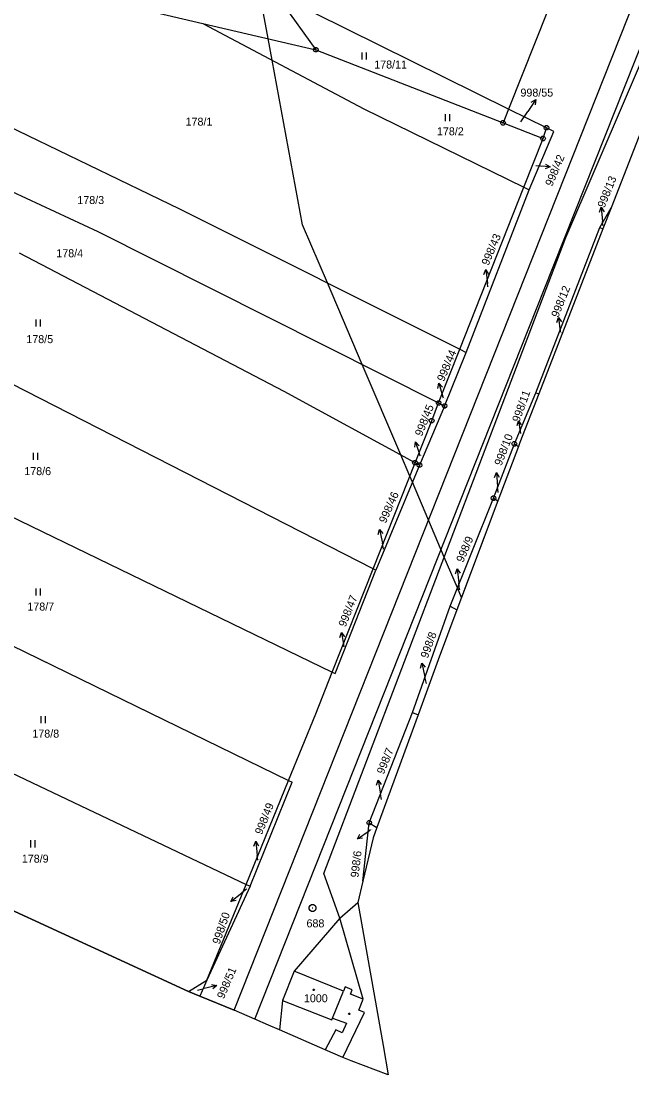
# Model space of a CAD drawing. Extents: x -755359 to -754474, y -1162585 to -1161655.
# Drawn here: x -755045.7 to -754916, y -1162585.2 to -1162361.4 of the extents above; entities that cross this region are included whole.
import ezdxf

# ---------------------------------------------------------------- set-up
doc = ezdxf.new("R2010")
doc.units = 0
for name, color, linetype in [('Vrstva 1', 7, 'Continuous'), ('Vrstva 11', 7, 'Continuous'), ('Vrstva 12', 7, 'Continuous'), ('Vrstva 2', 7, 'Continuous'), ('Vrstva 3', 7, 'Continuous'), ('Vrstva 4', 7, 'Continuous'), ('Vrstva 5', 7, 'Continuous'), ('Vrstva 6', 7, 'Continuous'), ('Vrstva 7', 7, 'Continuous'), ('Vrstva 8', 7, 'Continuous')]:
    doc.layers.add(name, color=color, linetype=linetype)

msp = doc.modelspace()

# ---------------------------------------------------------------- linework, layer by layer
at = {"layer": 'Vrstva 1'}
for p, q in [((-754930.02, -1162407.36), (-754870.17, -1162267.96)), ((-755096.49, -1162341), (-755007.12, -1162361.91)), ((-754942.18, -1162380.1), (-754991.59, -1162355.66)), ((-754991.59, -1162355.66), (-754983.11, -1162367.53)), ((-754933.79, -1162358.94), (-754942.18, -1162380.1)), ((-754904.19, -1162359.38), (-754920.39, -1162401.05)), ((-755007.12, -1162361.91), (-754972.93, -1162380.07)), ((-755007.12, -1162361.91), (-754983.11, -1162367.53)), ((-754983.11, -1162367.53), (-754943.35, -1162383.04)), ((-755065.93, -1162375.26), (-755012.09, -1162401.26)), ((-754972.93, -1162380.07), (-754938.92, -1162396.68)), ((-754942.18, -1162380.1), (-754943.35, -1162383.04)), ((-754934.1, -1162384.09), (-754942.18, -1162380.1)), ((-754943.35, -1162383.04), (-754934.85, -1162386.36)), ((-754934.85, -1162386.36), (-754934.1, -1162384.09)), ((-754932.57, -1162384.85), (-754934.1, -1162384.09)), ((-754938.92, -1162396.68), (-754934.85, -1162386.36)), ((-754937.81, -1162397.22), (-754932.57, -1162384.85)), ((-755066.17, -1162388.99), (-755029.41, -1162406.11)), ((-754952.51, -1162431.09), (-754938.92, -1162396.68)), ((-754951.16, -1162431.76), (-754937.81, -1162397.22)), ((-754938.92, -1162396.68), (-754937.81, -1162397.22)), ((-755012.09, -1162401.26), (-754952.51, -1162431.09)), ((-754922.76, -1162405.23), (-754920.39, -1162401.05)), ((-754920.39, -1162401.05), (-754922.13, -1162405.53)), ((-755029.41, -1162406.11), (-754957.02, -1162442.51)), ((-754936.37, -1162440.35), (-754922.76, -1162405.23)), ((-754922.13, -1162405.53), (-754935.75, -1162440.55)), ((-754922.76, -1162405.23), (-754922.13, -1162405.53)), ((-754981.37, -1162542.41), (-754930.02, -1162407.36)), ((-754989.82, -1162440.1), (-755046.04, -1162410.7)), ((-754957.02, -1162442.51), (-754952.51, -1162431.09)), ((-754952.51, -1162431.09), (-754951.16, -1162431.76)), ((-754955.75, -1162443.15), (-754951.16, -1162431.76)), ((-754970.94, -1162477.7), (-755047.73, -1162438.47)), ((-754962.03, -1162455.19), (-754989.82, -1162440.1)), ((-754958.5, -1162446.27), (-754957.02, -1162442.51)), ((-754957.02, -1162442.51), (-754955.75, -1162443.15)), ((-754940.94, -1162451.2), (-754936.37, -1162440.35)), ((-754935.75, -1162440.55), (-754939.77, -1162450.9)), ((-754936.37, -1162440.35), (-754935.75, -1162440.55)), ((-754955.75, -1162443.15), (-754961.09, -1162455.7)), ((-754962.03, -1162455.19), (-754958.5, -1162446.27)), ((-755081.44, -1162450.28), (-754979.63, -1162499.65)), ((-754945.37, -1162462.72), (-754940.94, -1162451.2)), ((-754940.94, -1162451.2), (-754940.08, -1162451.73)), ((-754939.77, -1162450.9), (-754940.08, -1162451.73)), ((-754940.08, -1162451.73), (-754944.44, -1162463.31)), ((-754970.94, -1162477.7), (-754962.03, -1162455.19)), ((-754961.09, -1162455.7), (-754970.36, -1162478)), ((-754961.09, -1162455.7), (-754962.03, -1162455.19)), ((-754954.58, -1162485.64), (-754945.37, -1162462.72)), ((-754944.44, -1162463.31), (-754953.13, -1162486.42)), ((-754945.37, -1162462.72), (-754944.44, -1162463.31)), ((-754979.63, -1162499.65), (-754970.94, -1162477.7)), ((-754979.01, -1162499.95), (-754970.36, -1162478)), ((-754970.36, -1162478), (-754970.94, -1162477.7)), ((-754962.59, -1162508.22), (-754954.58, -1162485.64)), ((-754953.13, -1162486.42), (-754957.12, -1162497.02)), ((-754954.58, -1162485.64), (-754953.13, -1162486.42)), ((-755054.02, -1162490.91), (-754988.9, -1162522.63)), ((-754957.12, -1162497.02), (-754961.39, -1162508.73)), ((-754983.12, -1162508.48), (-754979.63, -1162499.65)), ((-754979.63, -1162499.65), (-754979.01, -1162499.95)), ((-755083.94, -1162503.85), (-754997.93, -1162544.71)), ((-754988.9, -1162522.63), (-754983.12, -1162508.48)), ((-754971.75, -1162531.64), (-754962.59, -1162508.22)), ((-754961.39, -1162508.73), (-754970.12, -1162532.66)), ((-754962.59, -1162508.22), (-754961.39, -1162508.73)), ((-754997.93, -1162544.71), (-754988.9, -1162522.63)), ((-754997.07, -1162545.12), (-754988.1, -1162523.02)), ((-754988.9, -1162522.63), (-754988.1, -1162523.02)), ((-754973.09, -1162544.04), (-754971.75, -1162531.64)), ((-754971.75, -1162531.64), (-754970.12, -1162532.66)), ((-754970.12, -1162532.66), (-754970.91, -1162534.82)), ((-754970.91, -1162534.82), (-754973.09, -1162544.04)), ((-755064.06, -1162542.65), (-755010.16, -1162567.43)), ((-754978.01, -1162551.88), (-754981.37, -1162542.41)), ((-755006.25, -1162565.05), (-754997.93, -1162544.71)), ((-754997.07, -1162545.12), (-755006.25, -1162565.05)), ((-754997.93, -1162544.71), (-754997.07, -1162545.12)), ((-754973.09, -1162544.04), (-754974.17, -1162548.58)), ((-754978.01, -1162551.88), (-754974.17, -1162548.58)), ((-754974.17, -1162548.58), (-754968.81, -1162578.95)), ((-754978.01, -1162551.88), (-754987.73, -1162563.16)), ((-754987.73, -1162563.16), (-754990.19, -1162569.34)), ((-755010.16, -1162567.43), (-755006.25, -1162565.05)), ((-755006.25, -1162565.05), (-755007.72, -1162568.42)), ((-755010.16, -1162567.43), (-755007.72, -1162568.42)), ((-755007.72, -1162568.42), (-755000.46, -1162571.42)), ((-754990.19, -1162569.34), (-754990.79, -1162575.62)), ((-754996.07, -1162573.33), (-755000.46, -1162571.42)), ((-754993.17, -1162574.58), (-754996.07, -1162573.33)), ((-754990.79, -1162575.62), (-754993.17, -1162574.58)), ((-754981.12, -1162579.81), (-754990.79, -1162575.62)), ((-754968.81, -1162578.95), (-754967.71, -1162585.17)), ((-754977.36, -1162581.44), (-754981.12, -1162579.81)), ((-754975.59, -1162582.21), (-754977.36, -1162581.44)), ((-754967.71, -1162585.17), (-754975.59, -1162582.21))]:
    msp.add_line(p, q, dxfattribs=at)
at = {"layer": 'Vrstva 11'}
for p, q in [((-754993.26, -1162365.15), (-754995.39, -1162353.66)), ((-754904.19, -1162359.38), (-754920.39, -1162401.05)), ((-754992.41, -1162369.72), (-754993.26, -1162365.15)), ((-754985.92, -1162404.66), (-754992.41, -1162369.72)), ((-754920.39, -1162401.05), (-754922.13, -1162405.53)), ((-754980.66, -1162416.99), (-754985.92, -1162404.66)), ((-754922.13, -1162405.53), (-754935.75, -1162440.55)), ((-754973.27, -1162434.34), (-754980.66, -1162416.99)), ((-754965.08, -1162453.53), (-754973.27, -1162434.34)), ((-754935.75, -1162440.55), (-754939.77, -1162450.9)), ((-754939.77, -1162450.9), (-754940.08, -1162451.73)), ((-754963.16, -1162458.04), (-754965.08, -1162453.53)), ((-754940.08, -1162451.73), (-754944.44, -1162463.31)), ((-754962.6, -1162459.34), (-754963.16, -1162458.04)), ((-754955.83, -1162475.23), (-754962.6, -1162459.34)), ((-754944.44, -1162463.31), (-754952.16, -1162483.84)), ((-754953.03, -1162481.79), (-754955.83, -1162475.23)), ((-754952.16, -1162483.84), (-754953.03, -1162481.79)), ((-754952.16, -1162483.84), (-754953.13, -1162486.42)), ((-754953.13, -1162486.42), (-754957.12, -1162497.02)), ((-754957.12, -1162497.02), (-754961.39, -1162508.73)), ((-754961.39, -1162508.73), (-754970.12, -1162532.66)), ((-754970.12, -1162532.66), (-754970.91, -1162534.82)), ((-754970.91, -1162534.82), (-754973.09, -1162544.04)), ((-755010.16, -1162567.43), (-755064.06, -1162542.65)), ((-754973.09, -1162544.04), (-754974.17, -1162548.58)), ((-754974.17, -1162548.58), (-754968.81, -1162578.95)), ((-755007.72, -1162568.42), (-755010.16, -1162567.43)), ((-755000.46, -1162571.42), (-755007.72, -1162568.42)), ((-754996.07, -1162573.33), (-755000.46, -1162571.42)), ((-754993.17, -1162574.58), (-754996.07, -1162573.33)), ((-754990.79, -1162575.62), (-754993.17, -1162574.58)), ((-754981.12, -1162579.81), (-754990.79, -1162575.62)), ((-754968.81, -1162578.95), (-754967.71, -1162585.17)), ((-754977.36, -1162581.44), (-754981.12, -1162579.81)), ((-754975.59, -1162582.21), (-754977.36, -1162581.44)), ((-754967.71, -1162585.17), (-754975.59, -1162582.21))]:
    msp.add_line(p, q, dxfattribs=at)
at = {"layer": 'Vrstva 12'}
for p, q in [((-754987.73, -1162563.16), (-754990.19, -1162569.34)), ((-754977.24, -1162567.4), (-754987.73, -1162563.16)), ((-754979.54, -1162573.11), (-754977.24, -1162567.4)), ((-754990.19, -1162569.34), (-754979.67, -1162573.44)), ((-754979.67, -1162573.44), (-754979.54, -1162573.11))]:
    msp.add_line(p, q, dxfattribs=at)
at = {"layer": 'Vrstva 3'}
for p, q in [((-754973.32, -1162368.07), (-754973.32, -1162369.57)), ((-754972.32, -1162369.57), (-754972.32, -1162368.07)), ((-754955.63, -1162381.19), (-754955.63, -1162382.69)), ((-754954.63, -1162382.69), (-754954.63, -1162381.19)), ((-755042.57, -1162424.8), (-755042.57, -1162426.3)), ((-755041.57, -1162426.3), (-755041.57, -1162424.8)), ((-755043.16, -1162453.08), (-755043.16, -1162454.58)), ((-755042.16, -1162454.58), (-755042.16, -1162453.08)), ((-755042.6, -1162481.9), (-755042.6, -1162483.4)), ((-755041.6, -1162483.4), (-755041.6, -1162481.9)), ((-755041.54, -1162509), (-755041.54, -1162510.5)), ((-755040.54, -1162510.5), (-755040.54, -1162509)), ((-755043.69, -1162535.35), (-755043.69, -1162536.85)), ((-755042.69, -1162536.85), (-755042.69, -1162535.35))]:
    msp.add_line(p, q, dxfattribs=at)
at = {"layer": 'Vrstva 4'}
for p, q in [((-754973.06, -1162569.09), (-754978.01, -1162551.88)), ((-754977.24, -1162567.4), (-754987.73, -1162563.16)), ((-754979.54, -1162573.11), (-754977.24, -1162567.4)), ((-754976.86, -1162566.48), (-754977.24, -1162567.4)), ((-754975.36, -1162567.08), (-754976.86, -1162566.48)), ((-754975.74, -1162568.01), (-754975.36, -1162567.08)), ((-754990.19, -1162569.34), (-754979.67, -1162573.44)), ((-754973.06, -1162569.09), (-754975.74, -1162568.01)), ((-754974, -1162571.4), (-754973.06, -1162569.09)), ((-754977.36, -1162581.44), (-754972.76, -1162571.89)), ((-754972.76, -1162571.89), (-754974, -1162571.4)), ((-754979.67, -1162573.44), (-754979.54, -1162573.11)), ((-754979.54, -1162573.11), (-754976.57, -1162574.2)), ((-754976.57, -1162574.2), (-754977.49, -1162576.26)), ((-754978.86, -1162575.61), (-754981.12, -1162579.81)), ((-754977.49, -1162576.26), (-754978.86, -1162575.61))]:
    msp.add_line(p, q, dxfattribs=at)
at = {"layer": 'Vrstva 5'}
for points in [[(-754983.45, -1162566.98), (-754983.36, -1162567.13), (-754983.45, -1162567.28), (-754983.63, -1162567.28), (-754983.72, -1162567.13), (-754983.63, -1162566.98)], [(-754975.92, -1162572.07), (-754975.83, -1162572.22), (-754975.92, -1162572.37), (-754976.1, -1162572.37), (-754976.19, -1162572.22), (-754976.1, -1162572.07)]]:
    msp.add_lwpolyline(points, close=True, dxfattribs=at)
at = {"layer": 'Vrstva 6'}
for p, q in [((-755000.46, -1162571.42), (-754786.74, -1162032.64)), ((-754934.61, -1162418.42), (-754899.91, -1162330.95)), ((-754996.07, -1162573.33), (-754934.61, -1162418.42))]:
    msp.add_line(p, q, dxfattribs=at)
at = {"layer": 'Vrstva 7'}
for p, q in [((-754936.385, -1162378.094), (-754938.05, -1162380.59)), ((-754939.56, -1162382.84), (-754938.05, -1162380.59)), ((-754933.368, -1162392.353), (-754936.36, -1162392.13)), ((-754922.471, -1162400.961), (-754922.21, -1162403.95)), ((-754922.14, -1162404.8), (-754922.21, -1162403.95)), ((-754947.025, -1162414.192), (-754946.66, -1162417.17)), ((-754946.58, -1162417.83), (-754946.66, -1162417.17)), ((-754931.545, -1162424.332), (-754931.18, -1162427.31)), ((-754931.15, -1162427.55), (-754931.18, -1162427.31)), ((-754956.998, -1162438.311), (-754956.12, -1162441.18)), ((-754956.02, -1162441.51), (-754956.12, -1162441.18)), ((-754940.041, -1162446.317), (-754939.66, -1162449.02)), ((-754961.917, -1162450.777), (-754960.99, -1162453.63)), ((-754960.96, -1162453.72), (-754960.99, -1162453.63)), ((-754944.751, -1162457.291), (-754944.49, -1162460.28)), ((-754944.37, -1162461.51), (-754944.49, -1162460.28)), ((-754969.592, -1162469.345), (-754968.97, -1162472.28)), ((-754968.71, -1162473.56), (-754968.97, -1162472.28)), ((-754953.074, -1162477.727), (-754952.76, -1162480.71)), ((-754952.6, -1162482.15), (-754952.76, -1162480.71)), ((-754977.659, -1162491.217), (-754977.19, -1162494.18)), ((-754977.17, -1162494.31), (-754977.19, -1162494.18)), ((-754960.625, -1162497.757), (-754959.95, -1162500.68)), ((-754959.63, -1162502.08), (-754959.95, -1162500.68)), ((-754969.882, -1162522.586), (-754969.36, -1162525.54)), ((-754969.16, -1162526.69), (-754969.36, -1162525.54)), ((-754974.277, -1162535.017), (-754971.79, -1162533.34)), ((-754971.47, -1162533.12), (-754971.79, -1162533.34)), ((-754995.854, -1162535.567), (-754995.54, -1162538.55)), ((-754995.44, -1162539.55), (-754995.54, -1162538.55)), ((-755001.154, -1162548.337), (-754998.79, -1162546.49)), ((-754997.81, -1162545.72), (-754998.79, -1162546.49)), ((-755008.2, -1162567.18), (-755007.07, -1162566.91)), ((-755004.159, -1162566.183), (-755007.07, -1162566.91))]:
    msp.add_line(p, q, dxfattribs=at)
for points in [[(-754937.356, -1162378.649), (-754936.385, -1162378.094), (-754936.524, -1162379.204)], [(-754934.328, -1162391.78), (-754933.368, -1162392.353), (-754934.403, -1162392.777)], [(-754922.882, -1162402.001), (-754922.471, -1162400.961), (-754921.886, -1162401.914)], [(-754947.4, -1162415.246), (-754947.025, -1162414.192), (-754946.407, -1162415.124)], [(-754931.92, -1162425.386), (-754931.545, -1162424.332), (-754930.927, -1162425.264)], [(-754957.183, -1162439.414), (-754956.998, -1162438.311), (-754956.227, -1162439.121)], [(-754940.365, -1162447.281), (-754940.041, -1162446.317), (-754939.463, -1162447.154)], [(-754962.083, -1162451.882), (-754961.917, -1162450.777), (-754961.132, -1162451.573)], [(-754945.162, -1162458.331), (-754944.751, -1162457.291), (-754944.166, -1162458.244)], [(-754969.874, -1162470.427), (-754969.592, -1162469.345), (-754968.896, -1162470.22)], [(-754953.467, -1162478.773), (-754953.074, -1162477.727), (-754952.472, -1162478.669)], [(-754977.997, -1162492.283), (-754977.659, -1162491.217), (-754977.009, -1162492.126)], [(-754960.887, -1162498.844), (-754960.625, -1162497.757), (-754959.913, -1162498.619)], [(-754970.201, -1162523.658), (-754969.882, -1162522.586), (-754969.216, -1162523.483)], [(-754973.169, -1162534.873), (-754974.277, -1162535.017), (-754973.728, -1162534.043)], [(-754996.247, -1162536.613), (-754995.854, -1162535.567), (-754995.252, -1162536.509)], [(-755000.058, -1162548.115), (-755001.154, -1162548.337), (-755000.674, -1162547.327)], [(-755005.251, -1162565.941), (-755004.159, -1162566.183), (-755005.008, -1162566.911)]]:
    msp.add_lwpolyline(points, dxfattribs=at)
at = {"layer": 'Vrstva 8'}
for p, q in [((-754983.23, -1162367.53), (-754982.99, -1162367.53)), ((-754943.47, -1162383.04), (-754943.23, -1162383.04)), ((-754934.22, -1162384.09), (-754933.98, -1162384.09)), ((-754934.97, -1162386.36), (-754934.73, -1162386.36)), ((-754957.14, -1162442.51), (-754956.9, -1162442.51)), ((-754955.87, -1162443.15), (-754955.63, -1162443.15)), ((-754958.62, -1162446.27), (-754958.38, -1162446.27)), ((-754941.06, -1162451.2), (-754940.82, -1162451.2)), ((-754962.15, -1162455.19), (-754961.91, -1162455.19)), ((-754961.21, -1162455.7), (-754960.97, -1162455.7)), ((-754945.49, -1162462.72), (-754945.25, -1162462.72)), ((-754971.87, -1162531.64), (-754971.63, -1162531.64)), ((-754983.85, -1162549.72), (-754983.75, -1162549.72))]:
    msp.add_line(p, q, dxfattribs=at)
for points in [[(-754982.96, -1162367.05), (-754982.71, -1162367.23), (-754982.61, -1162367.52), (-754982.71, -1162367.81), (-754982.96, -1162367.99), (-754983.27, -1162367.99), (-754983.52, -1162367.81), (-754983.62, -1162367.52), (-754983.52, -1162367.23), (-754983.27, -1162367.05)], [(-754943.2, -1162382.56), (-754942.95, -1162382.74), (-754942.85, -1162383.03), (-754942.95, -1162383.32), (-754943.2, -1162383.5), (-754943.51, -1162383.5), (-754943.76, -1162383.32), (-754943.86, -1162383.03), (-754943.76, -1162382.74), (-754943.51, -1162382.56)], [(-754933.95, -1162383.61), (-754933.7, -1162383.79), (-754933.6, -1162384.08), (-754933.7, -1162384.37), (-754933.95, -1162384.55), (-754934.26, -1162384.55), (-754934.51, -1162384.37), (-754934.61, -1162384.08), (-754934.51, -1162383.79), (-754934.26, -1162383.61)], [(-754934.7, -1162385.88), (-754934.45, -1162386.06), (-754934.35, -1162386.35), (-754934.45, -1162386.64), (-754934.7, -1162386.82), (-754935.01, -1162386.82), (-754935.26, -1162386.64), (-754935.36, -1162386.35), (-754935.26, -1162386.06), (-754935.01, -1162385.88)], [(-754956.87, -1162442.03), (-754956.62, -1162442.21), (-754956.52, -1162442.5), (-754956.62, -1162442.79), (-754956.87, -1162442.97), (-754957.18, -1162442.97), (-754957.43, -1162442.79), (-754957.53, -1162442.5), (-754957.43, -1162442.21), (-754957.18, -1162442.03)], [(-754955.6, -1162442.67), (-754955.35, -1162442.85), (-754955.25, -1162443.14), (-754955.35, -1162443.43), (-754955.6, -1162443.61), (-754955.91, -1162443.61), (-754956.16, -1162443.43), (-754956.26, -1162443.14), (-754956.16, -1162442.85), (-754955.91, -1162442.67)], [(-754958.35, -1162445.79), (-754958.1, -1162445.97), (-754958, -1162446.26), (-754958.1, -1162446.55), (-754958.35, -1162446.73), (-754958.66, -1162446.73), (-754958.91, -1162446.55), (-754959.01, -1162446.26), (-754958.91, -1162445.97), (-754958.66, -1162445.79)], [(-754940.79, -1162450.72), (-754940.54, -1162450.9), (-754940.44, -1162451.19), (-754940.54, -1162451.48), (-754940.79, -1162451.66), (-754941.1, -1162451.66), (-754941.35, -1162451.48), (-754941.45, -1162451.19), (-754941.35, -1162450.9), (-754941.1, -1162450.72)], [(-754961.88, -1162454.71), (-754961.63, -1162454.89), (-754961.53, -1162455.18), (-754961.63, -1162455.47), (-754961.88, -1162455.65), (-754962.19, -1162455.65), (-754962.44, -1162455.47), (-754962.54, -1162455.18), (-754962.44, -1162454.89), (-754962.19, -1162454.71)], [(-754960.94, -1162455.22), (-754960.69, -1162455.4), (-754960.59, -1162455.69), (-754960.69, -1162455.98), (-754960.94, -1162456.16), (-754961.25, -1162456.16), (-754961.5, -1162455.98), (-754961.6, -1162455.69), (-754961.5, -1162455.4), (-754961.25, -1162455.22)], [(-754945.22, -1162462.24), (-754944.97, -1162462.42), (-754944.87, -1162462.71), (-754944.97, -1162463), (-754945.22, -1162463.18), (-754945.53, -1162463.18), (-754945.78, -1162463), (-754945.88, -1162462.71), (-754945.78, -1162462.42), (-754945.53, -1162462.24)], [(-754971.6, -1162531.16), (-754971.35, -1162531.34), (-754971.25, -1162531.63), (-754971.35, -1162531.92), (-754971.6, -1162532.1), (-754971.91, -1162532.1), (-754972.16, -1162531.92), (-754972.26, -1162531.63), (-754972.16, -1162531.34), (-754971.91, -1162531.16)], [(-754983.61, -1162549), (-754983.27, -1162549.19), (-754983.08, -1162549.53), (-754983.08, -1162549.92), (-754983.27, -1162550.26), (-754983.61, -1162550.45), (-754984, -1162550.45), (-754984.34, -1162550.26), (-754984.53, -1162549.92), (-754984.53, -1162549.53), (-754984.34, -1162549.19), (-754984, -1162549)]]:
    msp.add_lwpolyline(points, close=True, dxfattribs=at)

# ---------------------------------------------------------------- texts
at = {"layer": 'Vrstva 2'}
for s, height, p in [('178/11', 1.7, (-754970.695, -1162371.5)), ('178/1', 1.7, (-755010.767, -1162383.63)), ('178/2', 1.7, (-754957.377, -1162385.68)), ('998/55', 0.1, (-754939.81, -1162382.84)), ('998/42', 0.1, (-754936.346, -1162392.13)), ('178/3', 1.7, (-755033.757, -1162400.27)), ('998/13', 0.1, (-754922.126, -1162404.8)), ('178/4', 1.7, (-755038.217, -1162411.56)), ('998/43', 0.1, (-754946.566, -1162417.83)), ('178/5', 1.7, (-755044.587, -1162429.8)), ('998/12', 0.1, (-754931.136, -1162427.55)), ('998/44', 0.1, (-754956.006, -1162441.51)), ('998/11', 0.1, (-754939.646, -1162449.02)), ('998/45', 0.1, (-754960.946, -1162453.72)), ('178/6', 1.7, (-755045.017, -1162457.83)), ('998/9', 0.1, (-754952.586, -1162482.15)), ('178/7', 1.7, (-755044.367, -1162486.58)), ('998/8', 0.1, (-754959.616, -1162502.08)), ('178/8', 1.7, (-755043.307, -1162513.55)), ('998/7', 0.1, (-754969.146, -1162526.69)), ('998/6', 0.1, (-754971.456, -1162533.12)), ('178/9', 1.7, (-755045.547, -1162540.1)), ('998/49', 0.1, (-754995.426, -1162539.55)), ('998/51', 0.1, (-755008.186, -1162567.18)), ('1000', 1.7, (-754985.637, -1162569.74))]:
    msp.add_text(s, height=height, dxfattribs=at).set_placement(p)
for s, rotation, p in [('998/10', 73.79696, (-754944.366, -1162461.497)), ('998/46', 70.18733, (-754968.705, -1162473.547)), ('998/47', 70.18733, (-754977.165, -1162494.297)), ('998/50', 66.57769, (-754997.804, -1162545.707))]:
    msp.add_text(s, height=0.1, rotation=rotation, dxfattribs=at).set_placement(p)
at = {"layer": 'Vrstva 7'}
msp.add_text('998/55', height=1.7, dxfattribs=at).set_placement((-754939.643, -1162377.46))
for s, rotation, p in [('998/42', 67.15065, (-754932.908, -1162396.641)), ('998/13', 68.01009, (-754921.801, -1162401.201)), ('998/43', 66.97877, (-754946.437, -1162413.442)), ('998/12', 68.01009, (-754931.621, -1162424.497)), ('998/44', 66.97877, (-754955.897, -1162438.092)), ('998/11', 70.01544, (-754939.882, -1162446.724)), ('998/45', 68.01009, (-754960.581, -1162449.71)), ('998/10', 68.98412, (-754943.685, -1162455.968)), ('998/46', 66.00474, (-754968.243, -1162468.163)), ('998/9', 66.97877, (-754951.807, -1162476.502)), ('998/47', 68.01009, (-754976.811, -1162490.21)), ('998/8', 70.01544, (-754959.339, -1162496.837)), ('998/7', 68.01009, (-754968.671, -1162521.46)), ('998/49', 68.01009, (-754994.561, -1162534.29)), ('998/6', 83.02158, (-754974.062, -1162543.341)), ('998/50', 70.98947, (-755003.551, -1162557.564)), ('998/51', 66.97877, (-755002.633, -1162569.156))]:
    msp.add_text(s, height=1.7, rotation=rotation, dxfattribs=at).set_placement(p)
at = {"layer": 'Vrstva 8'}
msp.add_text('688', height=1.7, dxfattribs=at).set_placement((-754985.083, -1162553.84))

doc.saveas('drawing.dxf')
